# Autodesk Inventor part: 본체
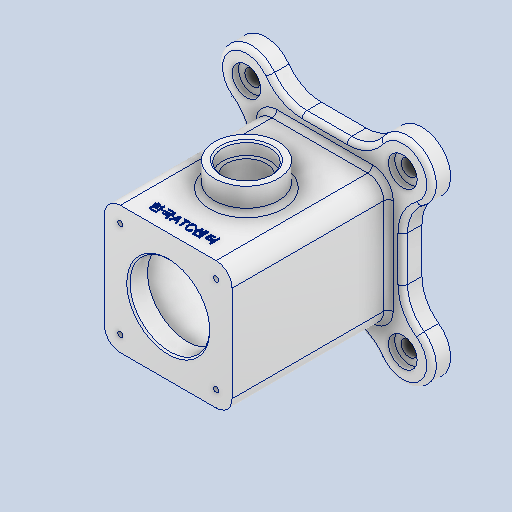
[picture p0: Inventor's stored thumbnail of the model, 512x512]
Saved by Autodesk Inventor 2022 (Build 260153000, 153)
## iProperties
Created: 2022-05
Part Number: 본체
Material: 알루미늄 6061
Document SubType Name: Modeling
Designer: Admin
Density: 2.7 g/cm^3
Appearance: 알루미늄 - 평지
Mass: 1070.84 g
Surface Area: 876.223 cm^2
Volume: 396.606 cm^3
Author: Admin
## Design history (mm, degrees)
sketch "스케치1"
  geometry: L1 (-68.6, 0)-(68.6, 0) reference; L2 (0, -68.6)-(0, 68.6) reference; L3 (-49, 49)-(49, 49); L4 (49, 49)-(49, -49); L5 (49, -49)-(-49, -49); L6 (-49, -49)-(-49, 49); L7 (-49, 49)-(49, -49); L8 (49, 49)-(-49, -49); 1 further point
  constraints: 12 end point, 2 midpoint, 2 parallel, 1 horizontal, 1 perpendicular
  dimensions: "d0" = 98 distance of L3.start L3.end; "d1" = 98 distance of L3.end L4.end
extrude "돌출1" new body sketch "스케치1" distance "d2" = 12; taper "d3" = 0 deg
sketch "스케치2"
  geometry: L1 (-40, 40)-(40, 40); L2 (40, 40)-(40, -40); L3 (40, -40)-(-40, -40); L4 (-40, -40)-(-40, 40); L5 (-40, 40)-(40, -40); L6 (40, 40)-(-40, -40); 1 further point
  constraints: 12 end point, 2 midpoint, 2 parallel, 1 horizontal, 1 perpendicular
  dimensions: "d4" = 80 distance of L1.start L1.end; "d5" = 80 distance of L1.end L2.end
extrude "돌출2" join sketch "스케치2" distance "d6" = 98; taper "d7" = 0 deg
node "작업 평면1"
sketch "스케치4"
  geometry: L1 (0, -22)-(0, 132) reference; L2 (-49, 12)-(49, 12) reference; C1 r 20 at (0, 61); 1 further point
  constraints: 1 centre point, 1 point on line
  dimensions: "d10" = 40 diameter of C1; "d11" = 49 distance from line of L2 C1.centre
extrude "돌출3" join sketch "스케치4" stored distance "d12" = 98; taper "d13" = 0 deg
sketch "스케치5"
  geometry: L1 (0, 83)-(0, -71) reference; L2 (49, 49)-(-49, 49) reference; 2 further points
  constraints: 1 point on line
  dimensions: "d14" = 49 distance from line of L2 point (0, 0)
hole "구멍1" sketch "스케치5" at (0, 0) diameter "d15" = 25; stored, may be unused: countersink angle "d19" = 90 deg, drill point angle "d21" = 0 deg; dims "d16" = 18, "d17" = 30, "d18" = 8, "d20" = 30
sketch "스케치6"
  geometry: L1 (0, -22)-(0, 132) reference; L2 (0, 110)-(25, 110); L3 (25, 110)-(25, 98); L4 (25, 98)-(0, 98); L5 (0, 98)-(0, 110); L6 (0, 98)-(35, 98); L7 (35, 98)-(35, 12); L8 (35, 12)-(0, 12); L9 (0, 12)-(0, 98); L10 (49, 0)-(-49, 0) reference; L11 (0, 12)-(25, 12); L12 (25, 12)-(25, 0); L13 (25, 0)-(0, 0); L14 (0, 0)-(0, 12); 4 further points
  constraints: 24 end point, 6 parallel, 3 horizontal, 3 perpendicular, 3 point on line
  dimensions: "d22" = 50 diameter of L12 L1; "d23" = 70 diameter of L7 L1; "d24" = 12 distance between parallel lines of L2 L4; "d25" = 12 distance between parallel lines of L10 L8; "d26" = 86 distance of L8.end L4.end
revolve "회전1" sketch "스케치6" stored, may be unused: angle "d27" = 90 deg
sketch "스케치7"
  geometry: L1 (0, -69.8)-(0, 75.8) reference; L2 (-68.6, 0)-(68.6, 0) reference; L3 (-30, 30)-(30, 30); L4 (30, 30)-(30, -30); L5 (30, -30)-(-30, -30); L6 (-30, -30)-(-30, 30); L7 (-30, 30)-(30, -30); L8 (30, 30)-(-30, -30); 6 further points
  constraints: 12 end point, 5 coincident, 2 midpoint, 2 parallel, 1 horizontal, 1 perpendicular
  dimensions: "d29" = 60 distance of L3.start L3.end; "d30" = 60 distance of L3.end L4.end
hole "구멍2" sketch "스케치7" at (30, 30), (-30, 30), (-30, -30), (30, -30) diameter "d31" = 3.242; stored, may be unused: countersink angle "d35" = 90 deg, drill point angle "d37" = 118 deg; dims "d32" = 8, "d33" = 30, "d34" = 8, "d36" = 10
sketch "스케치8"
  geometry: L1 (68.6, 0)-(-68.6, 0) reference; L2 (0, -69.8)-(0, 75.8) reference; L3 (0, 0)-(78.013, 78.013); L4 (-49, 49)-(49, 49) reference; C1 r 70 at (0, 0); C2 r 18 at (49, 49); 1 further point
  constraints: 2 centre point, 2 end point, 1 coincident
  dimensions: "d38" = 140 diameter of C1; "d39" = 45 deg angle of L1 L3; "d40" = 36 diameter of C2
extrude "돌출4" join sketch "스케치8" distance "d41" = 12; taper "d42" = 0 deg
fillet "모깎기1" dims "d43" = 25
fillet "모깎기2" dims "d47" = 25
sketch "스케치9"
  geometry: L1 (0, -93.8)-(0, 93.8) reference; L2 (93.8, 0)-(-93.8, 0) reference; L3 (30, 30)-(-30, 30); L4 (-30, 30)-(-30, -30); L5 (-30, -30)-(30, -30); L6 (30, -30)-(30, 30); L7 (30, 30)-(-30, -30); L8 (-30, 30)-(30, -30); C1 r 1.621 at (30, 30) reference; C2 r 1.621 at (30, -30) reference; C3 r 1.621 at (-30, -30) reference; C4 r 1.621 at (-30, 30) reference; 5 further points
  constraints: 12 end point, 4 coincident, 2 midpoint, 2 parallel, 1 horizontal, 1 perpendicular
  dimensions: "d48" = 60 distance of L5.end L3.start; "d49" = 60 distance of L4.end L5.end
hole "구멍3" sketch "스케치9" at (30, 30), (30, -30), (-30, -30), (-30, 30) diameter "d50" = 3.242; stored, may be unused: countersink angle "d54" = 90 deg, drill point angle "d56" = 118 deg; dims "d51" = 8, "d52" = 4, "d53" = 2, "d55" = 10
fillet "모깎기3" dims "d57" = 10
chamfer "모따기1" distance "d58" = 1; stored, may be unused: second distance "d59" = 2, angle "d60" = 45 deg
sketch "스케치10"
  geometry: A1 r 18 centre (49, 49) between (59.465, 34.355) and (34.355, 59.465) reference; A2 r 18 centre (-49, 49) between (-34.355, 59.465) and (-59.465, 34.355) reference; A3 r 18 centre (-49, -49) between (-59.465, -34.355) and (-34.355, -59.465) reference; A4 r 18 centre (49, -49) between (34.355, -59.465) and (59.465, -34.355) reference; 5 further points
  constraints: 4 coincident
hole "구멍4" sketch "스케치10" at (49, 49), (-49, 49), (-49, -49), (49, -49) diameter "d61" = 10; stored, may be unused: countersink angle "d65" = 90 deg, drill point angle "d67" = 0 deg; dims "d62" = 8, "d63" = 18, "d64" = 4, "d66" = 12
sketch "스케치11"
  geometry: L1 (30, 34)-(30, -120) reference; L2 (60, -98)-(0, -98) reference; 2 further points
  constraints: 1 point on line, 1 other
  dimensions: "d68" = 10 distance from line of L2 point (30, -88)
feature "엠보싱1" sketch "스케치11" dims "d0" = 98, "d1" = 98, "d69" = 0.5, "d70" = 0
fillet "모깎기4" dims "d71" = 3
node "솔리드1"
pattern_circular "원형 패턴1" dims angle "d45" = 360 deg
feature "A9D066F2-1C7D-4E18-AEED-F7BC21143FA4" dims "d15" = 25, "d16" = 18, "d17" = 30, "d18" = 8, "d19" = 90 deg, "d20" = 30, "d21" = 0
other parameters: "d9" = 55
